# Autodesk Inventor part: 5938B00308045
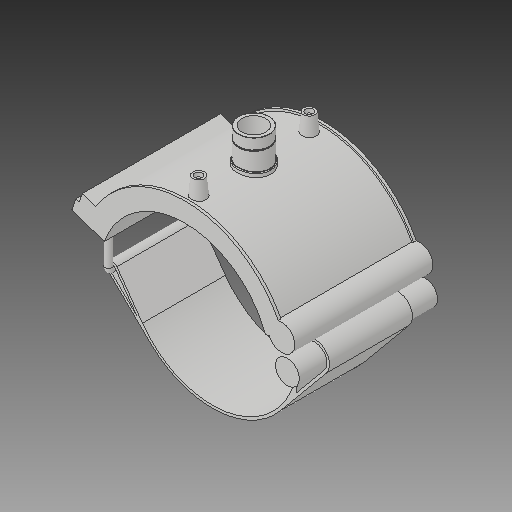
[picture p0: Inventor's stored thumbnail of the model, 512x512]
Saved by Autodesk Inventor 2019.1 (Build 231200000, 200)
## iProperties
Created: 2017-07
Part Number: 5938B00308045
Material: Generic
Description: PLASSON TRANSITION SADDLE 8''IPS x 1"NPT
Document SubType Name: Modeling
Designer: KIM
Density: 1 g/cm^3
Appearance: Default
Author: KIM
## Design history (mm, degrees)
derived "5938B.ipt"
feature "Solid1::5938B.ipt"
tag "TaggingFeature1"
body "Solid1"
other parameters: "d0" = 218.7, "d1" = 262.44, "d2" = 449.58, "d3" = 54.675, "d4" = 176.022, "d5" = 0, "d40" = 136.4688, "d41" = 42.4074, "d43" = 0, "d45" = 0, "d47" = 173.13, "d48" = 39.3783, "d50" = 0, "d78" = 153.22, "d79" = 15, "d80" = 70.4088, "d82" = 5 deg, "d84" = 4, "d85" = 14, "d86" = 0, "d87" = 3, "d88" = 0, "d96" = 267.6888, "d97" = 3.52044, "d98" = 0, "d102" = 0.90873, "d103" = 30.291, "d104" = 25.146, "d105" = 0, "d106" = 24.2328, "d108" = 0, "d109" = -13.97, "d111" = 0.5, "d112" = 0.5, "d113" = 0, "d114" = 0.5, "d117" = 0.30291, "d120" = 140 deg, "d121" = 24.228, "d122" = 20 deg, "d123" = 1049.76, "d124" = 157.464, "d126" = 0, "d143" = 225.261, "d145" = 33.64615, "d149" = 3.2805, "d150" = 37.01077, "d153" = 176.022, "d154" = 0, "d156" = 131.22, "d157" = 160 deg, "d159" = 8.748, "d161" = 3.2805, "d162" = 105.6132, "d163" = 0, "d164" = 109.35, "d167" = 21.87, "d168" = 128.01951, "d170" = 3.2805, "d172" = 0, "d173" = 1, "d175" = 109.35, "d176" = 20 deg, "d177" = 15.309, "d178" = 43.74, "d180" = 0, "d183" = 17.496, "d184" = 12.2472, "d185" = 57.20715, "d186" = 57.20715, "d187" = 131.22, "d188" = 13.122, "d189" = 15.309, "d190" = 0, "d191" = 157.464, "d193" = 8.748, "d194" = 4.48335, "d195" = 90 deg, "d197" = 0, "d199" = 0, "d_" = 218.7, "B_" = 179.832, "H_" = 41.91, "L_" = 176.022, "d_t" = 6, "G_" = 30.291, "d148" = 3.2805, "d160" = 3.2805, "d169" = 3.2805, "d192" = 8.748
